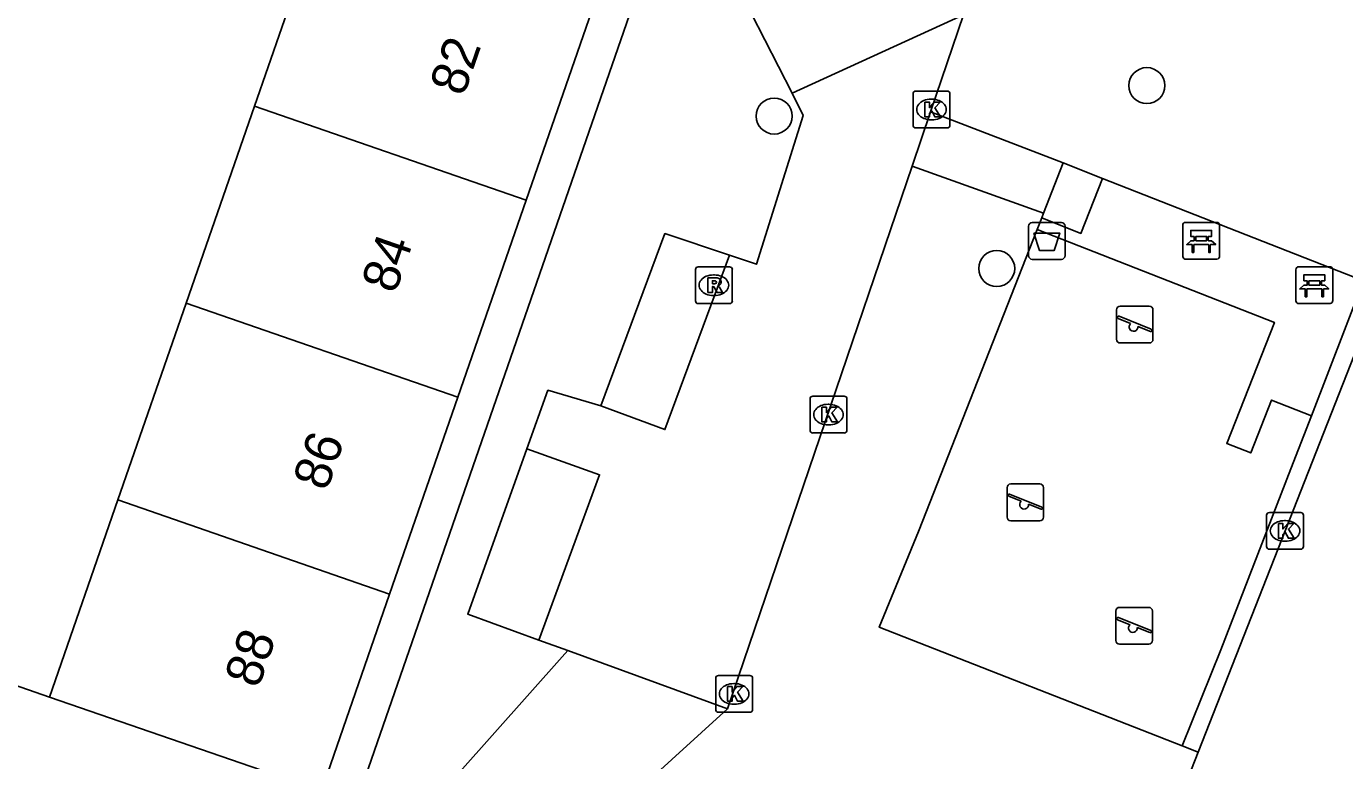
# Model space of a CAD drawing. Extents: x 160356 to 161355, y 381727 to 382845.
# Drawn here: x 160633.15 to 160668.94, y 382130.04 to 382149.99 of the extents above; entities that cross this region are included whole.
import ezdxf

# ---------------------------------------------------------------- set-up
doc = ezdxf.new("R2010")
doc.units = 0
for name, color, linetype in [('IMGEO_Afvalbak', 7, 'Continuous'), ('IMGEO_Bank', 7, 'Continuous'), ('IMGEO_Boom', 7, 'Continuous'), ('IMGEO_Groenvoorziening', 7, 'Continuous'), ('IMGEO_Hek', 7, 'Continuous'), ('IMGEO_Kolk', 7, 'Continuous'), ('IMGEO_Pand', 7, 'Continuous'), ('IMGEO_Pand_nummerreeks', 7, 'Continuous'), ('IMGEO_Parkeervlak_open', 7, 'Continuous'), ('IMGEO_Rioolput', 7, 'Continuous'), ('IMGEO_Speelvoorziening', 7, 'Continuous'), ('IMGEO_Voetpad_open', 7, 'Continuous'), ('IMGEO_Woonerf_open', 7, 'Continuous')]:
    doc.layers.add(name, color=color, linetype=linetype)

msp = doc.modelspace()

# ---------------------------------------------------------------- linework, layer by layer
at = {"layer": 'IMGEO_Afvalbak'}
for p, q in [((160660.461, 382144.659), (160661.251, 382144.659)), ((160661.251, 382144.659), (160660.461, 382144.659)), ((160660.361, 382143.759), (160660.361, 382144.559)), ((160660.361, 382144.559), (160660.361, 382143.759)), ((160661.351, 382144.559), (160661.351, 382143.759)), ((160661.351, 382143.759), (160661.351, 382144.559)), ((160661.251, 382143.659), (160660.461, 382143.659)), ((160660.461, 382143.659), (160661.251, 382143.659))]:
    msp.add_line(p, q, dxfattribs=at)
msp.add_lwpolyline([(160660.504, 382144.373), (160661.208, 382144.373), (160661.059, 382143.903), (160660.653, 382143.903), (160660.504, 382144.373)], dxfattribs=at)
for centre, start, end in [((160660.461, 382144.559), 90, 180), ((160660.461, 382144.559), 90, 180), ((160661.251, 382144.559), 0, 90), ((160661.251, 382144.559), 360, 90), ((160660.461, 382143.759), 180, 270), ((160660.461, 382143.759), 180, 270), ((160661.251, 382143.759), 270, 0), ((160661.251, 382143.759), 270, 0)]:
    msp.add_arc(centre, 0.1, start, end, dxfattribs=at)
at = {"layer": 'IMGEO_Bank'}
for p, q in [((160664.624, 382144.664), (160665.465, 382144.664)), ((160665.465, 382144.664), (160664.624, 382144.664)), ((160664.549, 382143.739), (160664.549, 382144.58)), ((160664.549, 382144.58), (160664.549, 382143.739)), ((160664.858, 382144.17), (160664.858, 382144.276)), ((160664.902, 382144.276), (160664.902, 382144.17)), ((160665.19, 382144.282), (160664.908, 382144.282)), ((160665.196, 382144.17), (160665.196, 382144.276)), ((160665.24, 382144.276), (160665.24, 382144.17)), ((160665.549, 382144.589), (160665.549, 382143.748)), ((160665.549, 382143.748), (160665.549, 382144.589)), ((160665.246, 382144.062), (160664.853, 382144.062)), ((160664.908, 382144.164), (160665.19, 382144.164)), ((160665.474, 382143.664), (160664.633, 382143.664)), ((160664.633, 382143.664), (160665.474, 382143.664)), ((160667.621, 382142.534), (160667.621, 382143.375)), ((160667.621, 382143.375), (160667.621, 382142.534)), ((160667.696, 382143.459), (160668.537, 382143.459)), ((160668.537, 382143.459), (160667.696, 382143.459)), ((160668.621, 382143.384), (160668.621, 382142.543)), ((160668.621, 382142.543), (160668.621, 382143.384)), ((160668.318, 382142.857), (160667.925, 382142.857)), ((160667.93, 382142.965), (160667.93, 382143.071)), ((160667.974, 382143.071), (160667.974, 382142.965)), ((160668.262, 382143.077), (160667.98, 382143.077)), ((160667.98, 382142.959), (160668.262, 382142.959)), ((160668.268, 382142.965), (160668.268, 382143.071)), ((160668.312, 382143.071), (160668.312, 382142.965)), ((160668.546, 382142.459), (160667.705, 382142.459)), ((160667.705, 382142.459), (160668.546, 382142.459))]:
    msp.add_line(p, q, dxfattribs=at)
for points in [[(160664.852, 382144.282), (160664.766, 382144.282), (160664.766, 382144.443), (160665.329, 382144.443), (160665.329, 382144.282), (160665.246, 382144.282)], [(160664.796, 382144.062), (160664.654, 382144.062), (160664.766, 382144.164), (160664.852, 382144.164)], [(160664.846, 382144.055), (160664.846, 382143.848), (160664.803, 382143.848), (160664.803, 382144.055)], [(160665.246, 382144.164), (160665.329, 382144.164), (160665.441, 382144.062), (160665.302, 382144.062)], [(160665.296, 382144.055), (160665.296, 382143.848), (160665.252, 382143.848), (160665.252, 382144.055)], [(160667.924, 382143.077), (160667.838, 382143.077), (160667.838, 382143.238), (160668.401, 382143.238), (160668.401, 382143.077), (160668.318, 382143.077)], [(160667.868, 382142.857), (160667.726, 382142.857), (160667.838, 382142.959), (160667.924, 382142.959)], [(160667.918, 382142.85), (160667.918, 382142.643), (160667.875, 382142.643), (160667.875, 382142.85)], [(160668.318, 382142.959), (160668.401, 382142.959), (160668.513, 382142.857), (160668.374, 382142.857)], [(160668.368, 382142.85), (160668.368, 382142.643), (160668.324, 382142.643), (160668.324, 382142.85)]]:
    msp.add_lwpolyline(points, dxfattribs=at)
for centre, radius, start, end in [((160664.627, 382144.586), 0.0779, 92.4484, 184.2845), ((160664.627, 382144.586), 0.0779, 92.4484, 184.2845), ((160665.471, 382144.586), 0.0779, 2.4484, 94.2845), ((160665.471, 382144.586), 0.0779, 2.4484, 94.2845), ((160664.851, 382144.275), 0.00671, 2.8957, 87.1043), ((160664.908, 382144.275), 0.00671, 92.8957, 177.1043), ((160665.19, 382144.275), 0.00671, 2.8957, 87.1043), ((160665.247, 382144.275), 0.00671, 92.8957, 177.1043), ((160664.796, 382144.055), 0.00671, 2.8957, 87.1043), ((160664.853, 382144.055), 0.00671, 92.8957, 177.1043), ((160664.851, 382144.171), 0.00671, 272.8957, 357.1043), ((160664.908, 382144.171), 0.00671, 182.8957, 267.1043), ((160665.19, 382144.171), 0.00671, 272.8957, 357.1043), ((160665.247, 382144.171), 0.00671, 182.8957, 267.1043), ((160665.245, 382144.055), 0.00671, 2.8957, 87.1043), ((160665.302, 382144.055), 0.00671, 92.8957, 177.1043), ((160664.627, 382143.742), 0.0779, 182.4484, 274.2845), ((160664.627, 382143.742), 0.0779, 182.4484, 274.2845), ((160665.471, 382143.742), 0.0779, 272.4484, 4.2845), ((160665.471, 382143.742), 0.0779, 272.4484, 4.2845), ((160667.699, 382143.381), 0.0779, 92.4484, 184.2845), ((160667.699, 382143.381), 0.0779, 92.4484, 184.2845), ((160668.543, 382143.381), 0.0779, 2.4484, 94.2845), ((160668.543, 382143.381), 0.0779, 2.4484, 94.2845), ((160667.868, 382142.85), 0.00671, 2.8957, 87.1043), ((160667.925, 382142.85), 0.00671, 92.8957, 177.1043), ((160667.923, 382143.07), 0.00671, 2.8957, 87.1043), ((160667.923, 382142.966), 0.00671, 272.8957, 357.1043), ((160667.98, 382143.07), 0.00671, 92.8957, 177.1043), ((160667.98, 382142.966), 0.00671, 182.8957, 267.1043), ((160668.262, 382143.07), 0.00671, 2.8957, 87.1043), ((160668.262, 382142.966), 0.00671, 272.8957, 357.1043), ((160668.319, 382143.07), 0.00671, 92.8957, 177.1043), ((160668.319, 382142.966), 0.00671, 182.8957, 267.1043), ((160668.317, 382142.85), 0.00671, 2.8957, 87.1043), ((160668.374, 382142.85), 0.00671, 92.8957, 177.1043), ((160667.699, 382142.537), 0.0779, 182.4484, 274.2845), ((160667.699, 382142.537), 0.0779, 182.4484, 274.2845), ((160668.543, 382142.537), 0.0779, 272.4484, 4.2845), ((160668.543, 382142.537), 0.0779, 272.4484, 4.2845)]:
    msp.add_arc(centre, radius, start, end, dxfattribs=at)
at = {"layer": 'IMGEO_Boom'}
for centre in [(160663.573, 382148.38), (160653.454, 382147.553), (160659.495, 382143.41)]:
    msp.add_circle(centre, 0.489, dxfattribs=at)
at = {"layer": 'IMGEO_Groenvoorziening'}
for points in [[(160662.368, 382145.86), (160661.302, 382146.278)], [(160660.717, 382144.788), (160660.766, 382144.913)], [(160664.529, 382130.44), (160656.307, 382133.663), (160657.374, 382136.267), (160660.593, 382144.471)]]:
    msp.add_lwpolyline(points, dxfattribs=at)
at = {"layer": 'IMGEO_Hek'}
msp.add_lwpolyline([(160657.374, 382136.267), (160656.307, 382133.663), (160664.529, 382130.44), (160665.577, 382133.048)], dxfattribs=at)
at = {"layer": 'IMGEO_Kolk'}
for p, q in [((160657.299, 382148.231), (160658.151, 382148.231)), ((160657.224, 382147.305), (160657.224, 382148.157)), ((160657.712, 382148.011), (160657.737, 382148.011)), ((160658.225, 382148.157), (160658.225, 382147.305)), ((160658.151, 382147.231), (160657.299, 382147.231)), ((160657.735, 382147.451), (160657.71, 382147.451)), ((160654.427, 382139.014), (160654.427, 382139.866)), ((160654.502, 382139.94), (160655.354, 382139.94)), ((160654.915, 382139.72), (160654.94, 382139.72)), ((160655.428, 382139.866), (160655.428, 382139.014)), ((160655.354, 382138.94), (160654.502, 382138.94)), ((160654.938, 382139.16), (160654.913, 382139.16)), ((160666.899, 382136.779), (160667.751, 382136.779)), ((160666.824, 382135.853), (160666.824, 382136.705)), ((160667.312, 382136.559), (160667.337, 382136.559)), ((160667.825, 382136.705), (160667.825, 382135.853)), ((160667.751, 382135.779), (160666.899, 382135.779)), ((160667.335, 382135.999), (160667.31, 382135.999)), ((160651.865, 382131.424), (160651.865, 382132.276)), ((160651.94, 382132.35), (160652.792, 382132.35)), ((160652.353, 382132.13), (160652.378, 382132.13)), ((160652.866, 382132.276), (160652.866, 382131.424)), ((160652.376, 382131.57), (160652.351, 382131.57)), ((160652.792, 382131.35), (160651.94, 382131.35))]:
    msp.add_line(p, q, dxfattribs=at)
for points in [[(160657.299, 382148.231), (160658.151, 382148.231)], [(160657.224, 382147.305), (160657.224, 382148.157)], [(160657.545, 382147.931), (160657.668, 382147.931), (160657.668, 382147.78), (160657.798, 382147.931), (160657.962, 382147.931), (160657.816, 382147.78), (160657.969, 382147.531), (160657.817, 382147.531), (160657.732, 382147.695), (160657.668, 382147.628), (160657.668, 382147.531), (160657.545, 382147.531), (160657.545, 382147.931)], [(160658.225, 382148.157), (160658.225, 382147.305)], [(160658.151, 382147.231), (160657.299, 382147.231)], [(160654.427, 382139.014), (160654.427, 382139.866)], [(160654.502, 382139.94), (160655.354, 382139.94)], [(160654.748, 382139.64), (160654.871, 382139.64), (160654.871, 382139.489), (160655.001, 382139.64), (160655.165, 382139.64), (160655.019, 382139.489), (160655.172, 382139.24), (160655.02, 382139.24), (160654.935, 382139.404), (160654.871, 382139.337), (160654.871, 382139.24), (160654.748, 382139.24), (160654.748, 382139.64)], [(160655.428, 382139.866), (160655.428, 382139.014)], [(160655.354, 382138.94), (160654.502, 382138.94)], [(160666.899, 382136.779), (160667.751, 382136.779)], [(160666.824, 382135.853), (160666.824, 382136.705)], [(160667.145, 382136.479), (160667.268, 382136.479), (160667.268, 382136.328), (160667.398, 382136.479), (160667.562, 382136.479), (160667.416, 382136.328), (160667.569, 382136.079), (160667.417, 382136.079), (160667.332, 382136.243), (160667.268, 382136.176), (160667.268, 382136.079), (160667.145, 382136.079), (160667.145, 382136.479)], [(160667.825, 382136.705), (160667.825, 382135.853)], [(160667.751, 382135.779), (160666.899, 382135.779)], [(160651.865, 382131.424), (160651.865, 382132.276)], [(160651.94, 382132.35), (160652.792, 382132.35)], [(160652.866, 382132.276), (160652.866, 382131.424)], [(160652.186, 382132.05), (160652.309, 382132.05), (160652.309, 382131.899), (160652.439, 382132.05), (160652.603, 382132.05), (160652.457, 382131.899), (160652.61, 382131.65), (160652.458, 382131.65), (160652.373, 382131.814), (160652.309, 382131.747), (160652.309, 382131.65), (160652.186, 382131.65), (160652.186, 382132.05)], [(160652.792, 382131.35), (160651.94, 382131.35)]]:
    msp.add_lwpolyline(points, dxfattribs=at)
for centre, start, end in [((160657.301, 382148.155), 91.552, 178.448), ((160657.301, 382148.155), 91.552, 178.448), ((160658.149, 382148.155), 1.552, 88.448), ((160658.149, 382148.155), 1.552, 88.448), ((160657.301, 382147.307), 181.552, 268.448), ((160657.301, 382147.307), 181.552, 268.448), ((160658.149, 382147.307), 271.552, 358.448), ((160658.149, 382147.307), 271.552, 358.448), ((160654.504, 382139.864), 91.552, 178.448), ((160654.504, 382139.864), 91.552, 178.448), ((160655.352, 382139.864), 1.552, 88.448), ((160655.352, 382139.864), 1.552, 88.448), ((160654.504, 382139.016), 181.552, 268.448), ((160654.504, 382139.016), 181.552, 268.448), ((160655.352, 382139.016), 271.552, 358.448), ((160655.352, 382139.016), 271.552, 358.448), ((160666.901, 382136.703), 91.552, 178.448), ((160666.901, 382136.703), 91.552, 178.448), ((160667.749, 382136.703), 1.552, 88.448), ((160667.749, 382136.703), 1.552, 88.448), ((160666.901, 382135.855), 181.552, 268.448), ((160666.901, 382135.855), 181.552, 268.448), ((160667.749, 382135.855), 271.552, 358.448), ((160667.749, 382135.855), 271.552, 358.448), ((160651.942, 382132.274), 91.552, 178.448), ((160651.942, 382132.274), 91.552, 178.448), ((160652.79, 382132.274), 1.552, 88.448), ((160652.79, 382132.274), 1.552, 88.448), ((160651.942, 382131.426), 181.552, 268.448), ((160651.942, 382131.426), 181.552, 268.448), ((160652.79, 382131.426), 271.552, 358.448), ((160652.79, 382131.426), 271.552, 358.448)]:
    msp.add_arc(centre, 0.0765, start, end, dxfattribs=at)
for centre, major_axis, ratio, start_param, end_param in [((160657.711, 382147.731), (-0.387, 0.002), 0.722429, 4.712389, 7.853982), ((160657.736, 382147.731), (-0.39, 0.002), 0.717154, 1.570796, 4.712389), ((160654.914, 382139.44), (-0.387, 0.002), 0.722429, 4.712389, 7.853982), ((160654.939, 382139.44), (-0.39, 0.002), 0.717154, 1.570796, 4.712389), ((160667.311, 382136.279), (-0.387, 0.002), 0.722429, 4.712389, 7.853982), ((160667.336, 382136.279), (-0.39, 0.002), 0.717154, 1.570796, 4.712389), ((160652.352, 382131.85), (-0.387, 0.002), 0.722429, 4.712389, 7.853982), ((160652.377, 382131.85), (-0.39, 0.002), 0.717154, 1.570796, 4.712389)]:
    msp.add_ellipse(centre, major_axis=major_axis, ratio=ratio, start_param=start_param, end_param=end_param, dxfattribs=at)
at = {"layer": 'IMGEO_Pand'}
for points in [[(160641.193, 382153.178), (160639.338, 382147.824)], [(160648.573, 382150.623), (160646.719, 382145.27)], [(160639.338, 382147.824), (160637.484, 382142.471)], [(160639.338, 382147.824), (160646.719, 382145.27)], [(160646.719, 382145.27), (160644.864, 382139.917)], [(160637.484, 382142.471), (160635.63, 382137.119)], [(160644.864, 382139.917), (160637.484, 382142.471)], [(160644.864, 382139.917), (160643.011, 382134.564)], [(160635.63, 382137.119), (160633.776, 382131.765)], [(160643.011, 382134.564), (160635.63, 382137.119)], [(160643.011, 382134.564), (160641.156, 382129.211)], [(160633.776, 382131.765), (160630.233, 382132.991), (160628.38, 382127.637), (160629, 382127.423)], [(160641.156, 382129.211), (160633.776, 382131.765)]]:
    msp.add_lwpolyline(points, dxfattribs=at)
at = {"layer": 'IMGEO_Parkeervlak_open'}
for points in [[(160652.241, 382143.773), (160650.485, 382139.034), (160648.749, 382139.677)], [(160646.738, 382138.508), (160648.71, 382137.804), (160647.065, 382133.311)]]:
    msp.add_lwpolyline(points, dxfattribs=at)
at = {"layer": 'IMGEO_Rioolput'}
for p, q in [((160651.315, 382142.53), (160651.315, 382143.382)), ((160651.39, 382143.456), (160652.242, 382143.456)), ((160651.803, 382143.236), (160651.828, 382143.236)), ((160652.316, 382143.382), (160652.316, 382142.53)), ((160652.242, 382142.456), (160651.39, 382142.456)), ((160651.826, 382142.676), (160651.801, 382142.676))]:
    msp.add_line(p, q, dxfattribs=at)
for points in [[(160651.315, 382142.53), (160651.315, 382143.382)], [(160651.39, 382143.456), (160652.242, 382143.456)], [(160652.316, 382143.382), (160652.316, 382142.53)], [(160651.904, 382143.154), (160651.652, 382143.156), (160651.652, 382142.756)], [(160651.652, 382142.756), (160651.776, 382142.756), (160651.776, 382142.918), (160651.787, 382142.918)], [(160651.83, 382143.075), (160651.776, 382143.075), (160651.776, 382142.994)], [(160651.776, 382142.994), (160651.828, 382142.994)], [(160651.834, 382142.889), (160651.905, 382142.756), (160652.045, 382142.756), (160651.98, 382142.882)], [(160652.242, 382142.456), (160651.39, 382142.456)]]:
    msp.add_lwpolyline(points, dxfattribs=at)
for centre, radius, start, end in [((160651.392, 382143.38), 0.0765, 91.552, 178.448), ((160651.392, 382143.38), 0.0765, 91.552, 178.448), ((160652.24, 382143.38), 0.0765, 1.552, 88.448), ((160652.24, 382143.38), 0.0765, 1.552, 88.448), ((160651.786, 382142.865), 0.0533, 26.0293, 88.6989), ((160651.812, 382143.183), 0.19, 274.7715, 282.9687), ((160651.836, 382142.979), 0.0964, 77.0061, 93.1865), ((160651.85, 382143.036), 0.0378, 276.6634, 79.6772), ((160651.903, 382143.044), 0.109, 350.3612, 89.416), ((160651.901, 382143.044), 0.112, 277.5842, 350.9817), ((160651.885, 382142.829), 0.108, 29.5134, 73.7905), ((160651.392, 382142.532), 0.0765, 181.552, 268.448), ((160651.392, 382142.532), 0.0765, 181.552, 268.448), ((160652.24, 382142.532), 0.0765, 271.552, 358.448), ((160652.24, 382142.532), 0.0765, 271.552, 358.448)]:
    msp.add_arc(centre, radius, start, end, dxfattribs=at)
for centre, major_axis, ratio, start_param, end_param in [((160651.802, 382142.956), (-0.387, 0.002), 0.722429, 4.712389, 7.853982), ((160651.827, 382142.956), (-0.39, 0.002), 0.717154, 1.570796, 4.712389)]:
    msp.add_ellipse(centre, major_axis=major_axis, ratio=ratio, start_param=start_param, end_param=end_param, dxfattribs=at)
at = {"layer": 'IMGEO_Speelvoorziening'}
for p, q in [((160662.749, 382141.486), (160662.749, 382142.286)), ((160662.749, 382142.286), (160662.749, 382141.486)), ((160662.818, 382142.111), (160663.694, 382141.758)), ((160662.849, 382142.386), (160663.639, 382142.386)), ((160663.639, 382142.386), (160662.849, 382142.386)), ((160663.739, 382142.286), (160663.739, 382141.486)), ((160663.739, 382141.486), (160663.739, 382142.286)), ((160663.132, 382141.914), (160662.793, 382142.051)), ((160663.67, 382141.698), (160663.33, 382141.835)), ((160663.639, 382141.386), (160662.849, 382141.386)), ((160662.849, 382141.386), (160663.639, 382141.386)), ((160659.777, 382136.655), (160659.777, 382137.455)), ((160659.777, 382137.455), (160659.777, 382136.655)), ((160659.877, 382137.555), (160660.667, 382137.555)), ((160660.667, 382137.555), (160659.877, 382137.555)), ((160660.767, 382137.455), (160660.767, 382136.655)), ((160660.767, 382136.655), (160660.767, 382137.455)), ((160660.16, 382137.083), (160659.821, 382137.22)), ((160659.846, 382137.28), (160660.722, 382136.927)), ((160660.698, 382136.867), (160660.358, 382137.004)), ((160660.667, 382136.555), (160659.877, 382136.555)), ((160659.877, 382136.555), (160660.667, 382136.555)), ((160662.732, 382133.302), (160662.732, 382134.102)), ((160662.732, 382134.102), (160662.732, 382133.302)), ((160663.115, 382133.73), (160662.776, 382133.867)), ((160662.801, 382133.927), (160663.677, 382133.574)), ((160662.832, 382134.202), (160663.622, 382134.202)), ((160663.622, 382134.202), (160662.832, 382134.202)), ((160663.722, 382134.102), (160663.722, 382133.302)), ((160663.722, 382133.302), (160663.722, 382134.102)), ((160663.653, 382133.514), (160663.313, 382133.651)), ((160663.622, 382133.202), (160662.832, 382133.202)), ((160662.832, 382133.202), (160663.622, 382133.202))]:
    msp.add_line(p, q, dxfattribs=at)
for centre, radius, start, end in [((160662.849, 382142.286), 0.1, 90, 180), ((160662.849, 382142.286), 0.1, 90, 180), ((160662.806, 382142.081), 0.0327, 68.078, 248.078), ((160663.639, 382142.286), 0.1, 0, 90), ((160663.639, 382142.286), 0.1, 360, 90), ((160663.211, 382141.824), 0.12, 130.9928, 5.1632), ((160663.682, 382141.728), 0.0327, 248.078, 68.078), ((160662.849, 382141.486), 0.1, 180, 270), ((160662.849, 382141.486), 0.1, 180, 270), ((160663.639, 382141.486), 0.1, 270, 0), ((160663.639, 382141.486), 0.1, 270, 0), ((160659.877, 382137.455), 0.1, 90, 180), ((160659.877, 382137.455), 0.1, 90, 180), ((160660.667, 382137.455), 0.1, 0, 90), ((160660.667, 382137.455), 0.1, 360, 90), ((160659.834, 382137.25), 0.0327, 68.078, 248.078), ((160660.239, 382136.993), 0.12, 130.9928, 5.1632), ((160660.71, 382136.897), 0.0327, 248.078, 68.078), ((160659.877, 382136.655), 0.1, 180, 270), ((160659.877, 382136.655), 0.1, 180, 270), ((160660.667, 382136.655), 0.1, 270, 0), ((160660.667, 382136.655), 0.1, 270, 0), ((160662.832, 382134.102), 0.1, 90, 180), ((160662.832, 382134.102), 0.1, 90, 180), ((160662.789, 382133.897), 0.0327, 68.078, 248.078), ((160663.622, 382134.102), 0.1, 0, 90), ((160663.622, 382134.102), 0.1, 360, 90), ((160663.194, 382133.64), 0.12, 130.9928, 5.1632), ((160663.665, 382133.544), 0.0327, 248.078, 68.078), ((160662.832, 382133.302), 0.1, 180, 270), ((160662.832, 382133.302), 0.1, 180, 270), ((160663.622, 382133.302), 0.1, 270, 0), ((160663.622, 382133.302), 0.1, 270, 0)]:
    msp.add_arc(centre, radius, start, end, dxfattribs=at)
at = {"layer": 'IMGEO_Voetpad_open'}
for points in [[(160655.119, 382166.468), (160634.794, 382107.787)], [(160654.086, 382155.763), (160652.456, 382151.083), (160653.938, 382148.171)], [(160653.938, 382148.171), (160654.244, 382147.569), (160652.976, 382143.527), (160652.241, 382143.773)], [(160657.203, 382146.188), (160657.701, 382147.664)], [(160661.302, 382146.278), (160657.701, 382147.664)], [(160660.766, 382144.913), (160657.203, 382146.188)], [(160661.302, 382146.278), (160660.766, 382144.913)], [(160662.368, 382145.86), (160661.783, 382144.362), (160660.717, 382144.788)], [(160669.459, 382143.077), (160662.368, 382145.86)], [(160660.593, 382144.471), (160660.717, 382144.788)], [(160648.749, 382139.677), (160650.485, 382144.361), (160652.241, 382143.773)], [(160668.039, 382139.409), (160666.956, 382139.835), (160666.393, 382138.397), (160665.744, 382138.652), (160667.035, 382141.943), (160660.593, 382144.471)], [(160669.923, 382142.895), (160664.967, 382130.268)], [(160669.459, 382143.077), (160668.039, 382139.409)], [(160648.749, 382139.677), (160647.308, 382140.103), (160646.738, 382138.508)], [(160668.039, 382139.409), (160667.482, 382137.97), (160665.577, 382133.048), (160664.529, 382130.44)], [(160647.065, 382133.311), (160645.133, 382134.015), (160646.738, 382138.508)], [(160647.065, 382133.311), (160647.848, 382133.026)], [(160647.848, 382133.026), (160647.698, 382132.857), (160644.92, 382129.732), (160644.447, 382128.448)], [(160664.529, 382130.44), (160664.967, 382130.268)]]:
    msp.add_lwpolyline(points, dxfattribs=at)
at = {"layer": 'IMGEO_Woonerf_open'}
for points in [[(160653.938, 382148.171), (160658.593, 382150.306)], [(160657.701, 382147.664), (160658.593, 382150.306)], [(160652.183, 382131.447), (160657.203, 382146.188)], [(160647.848, 382133.026), (160652.183, 382131.447)], [(160648.46, 382128.049), (160652.183, 382131.447)], [(160664.967, 382130.268), (160660.821, 382119.703)]]:
    msp.add_lwpolyline(points, dxfattribs=at)

# ---------------------------------------------------------------- texts
at = {"layer": 'IMGEO_Pand_nummerreeks'}
for s, p in [('82', (160645.019, 382148.061)), ('84', (160643.162, 382142.698)), ('86', (160641.304, 382137.334)), ('88', (160639.447, 382131.973))]:
    msp.add_text(s, height=1, rotation=70.8959, dxfattribs=at).set_placement(p)

doc.saveas('drawing.dxf')
